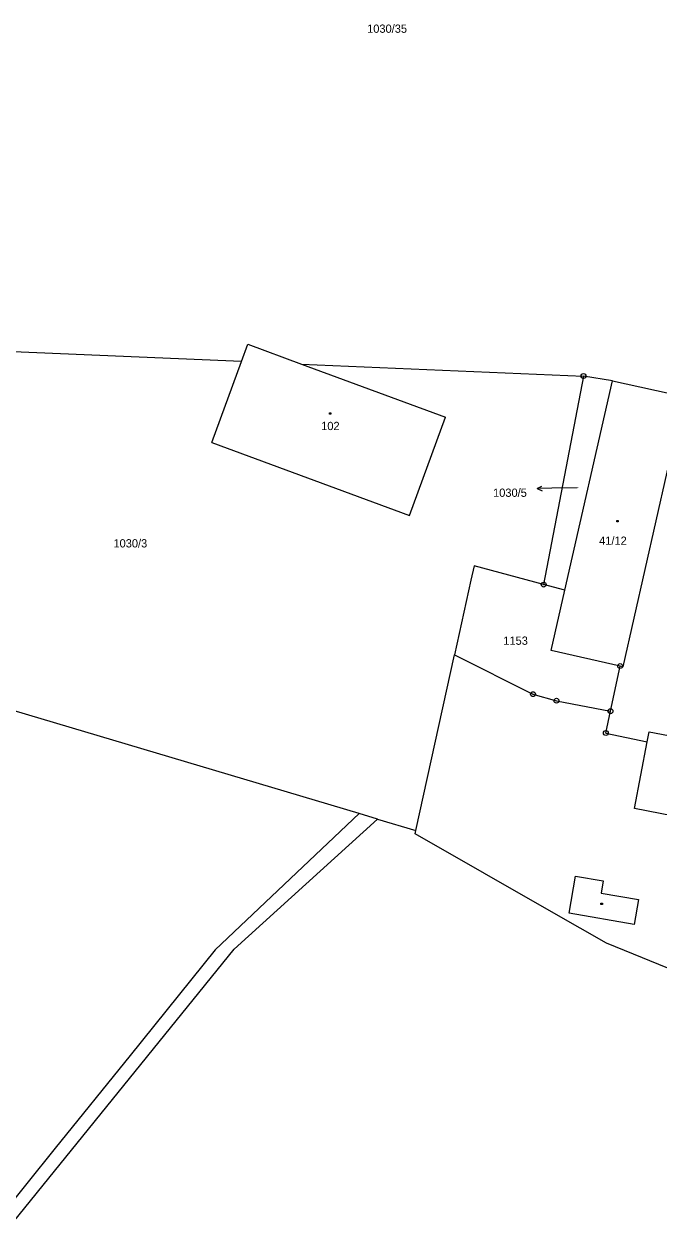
# Model space of a CAD drawing. Extents: x -794142 to -791199, y -1109267 to -1105626.
# Drawn here: x -791827.8 to -791697.1, y -1108632.2 to -1108384.2 of the extents above; entities that cross this region are included whole.
import ezdxf

# ---------------------------------------------------------------- set-up
doc = ezdxf.new("R2010")
doc.units = 0
for name, color, linetype in [('Komunikace', 7, 'Continuous'), ('Vrstva 1', 7, 'Continuous'), ('Vrstva 14', 7, 'Continuous'), ('Vrstva 15', 7, 'Continuous'), ('Vrstva 16', 7, 'Continuous'), ('Vrstva 2', 7, 'Continuous'), ('Vrstva 25', 7, 'Continuous'), ('Vrstva 28', 7, 'Continuous')]:
    doc.layers.add(name, color=color, linetype=linetype)

msp = doc.modelspace()

# ---------------------------------------------------------------- linework, layer by layer
at = {"layer": 'Komunikace'}
msp.add_line((-791713.89, -1108479.67), (-791719.17, -1108479.75), dxfattribs=at)
at = {"layer": 'Vrstva 1'}
for p, q in [((-791783.06, -1108453.63), (-791891.95, -1108449)), ((-791783.06, -1108453.63), (-791781.75, -1108450.09)), ((-791781.75, -1108450.09), (-791770.71, -1108454.16)), ((-791789.2, -1108470.31), (-791783.06, -1108453.63)), ((-791770.71, -1108454.16), (-791741.02, -1108465.1)), ((-791770.71, -1108454.16), (-791712.63, -1108456.63)), ((-791712.63, -1108456.63), (-791720.83, -1108499.57)), ((-791716.48, -1108500.74), (-791706.63, -1108457.59)), ((-791706.63, -1108457.59), (-791712.63, -1108456.63)), ((-791706.63, -1108457.59), (-791691.93, -1108460.85)), ((-791748.47, -1108485.32), (-791741.02, -1108465.1)), ((-791789.2, -1108470.31), (-791748.47, -1108485.32)), ((-791735.15, -1108495.73), (-791735.8, -1108498.66)), ((-791720.83, -1108499.57), (-791735.15, -1108495.73)), ((-791735.8, -1108498.66), (-791739.18, -1108514.04)), ((-791716.48, -1108500.74), (-791720.83, -1108499.57)), ((-791719.31, -1108513.12), (-791716.48, -1108500.74)), ((-791747.14, -1108550.19), (-791739.18, -1108514.04)), ((-791739.18, -1108514.04), (-791723.03, -1108522.13)), ((-791705.07, -1108516.34), (-791719.31, -1108513.12)), ((-791758.83, -1108546.71), (-791859.39, -1108516.79)), ((-791707.05, -1108525.63), (-791705.07, -1108516.34)), ((-791723.03, -1108522.13), (-791718.17, -1108523.48)), ((-791718.17, -1108523.48), (-791707.05, -1108525.63)), ((-791708.03, -1108530.13), (-791707.05, -1108525.63)), ((-791708.03, -1108530.13), (-791699.48, -1108531.91)), ((-791702.12, -1108545.66), (-791699.48, -1108531.91)), ((-791758.83, -1108546.71), (-791788.47, -1108574.78)), ((-791755.08, -1108547.83), (-791758.83, -1108546.71)), ((-791666.86, -1108552.44), (-791702.12, -1108545.66)), ((-791784.56, -1108574.59), (-791755.08, -1108547.83)), ((-791755.08, -1108547.83), (-791747.14, -1108550.19)), ((-791747.3, -1108550.89), (-791747.14, -1108550.19)), ((-791718.71, -1108567.18), (-791747.3, -1108550.89)), ((-791707.85, -1108573.38), (-791718.71, -1108567.18)), ((-791831.17, -1108632.21), (-791784.56, -1108574.59)), ((-791685.58, -1108582.47), (-791707.85, -1108573.38)), ((-791788.47, -1108574.78), (-791805.99, -1108596.53)), ((-791805.99, -1108596.53), (-791821.46, -1108615.59)), ((-791821.46, -1108615.59), (-791833.22, -1108630.17))]:
    msp.add_line(p, q, dxfattribs=at)
msp.add_lwpolyline([(-791699.48, -1108531.91), (-791699.09, -1108529.87), (-791662.54, -1108536.84), (-791662.89, -1108538.71)], dxfattribs=at)
at = {"layer": 'Vrstva 16'}
for p, q in [((-791722.169, -1108479.797), (-791721.177, -1108479.281)), ((-791719.17, -1108479.75), (-791722.169, -1108479.797)), ((-791722.169, -1108479.797), (-791721.161, -1108480.281))]:
    msp.add_line(p, q, dxfattribs=at)
at = {"layer": 'Vrstva 2'}
for p, q in [((-791693.19, -1108466.42), (-791704.49, -1108516.47)), ((-791704.49, -1108516.47), (-791705.07, -1108516.34)), ((-791715.55, -1108567.23), (-791714.3, -1108559.62)), ((-791714.3, -1108559.62), (-791708.58, -1108560.58)), ((-791708.58, -1108560.58), (-791709.01, -1108563.12)), ((-791709.01, -1108563.12), (-791701.3, -1108564.43)), ((-791701.3, -1108564.43), (-791702.17, -1108569.51)), ((-791702.17, -1108569.51), (-791715.55, -1108567.23))]:
    msp.add_line(p, q, dxfattribs=at)
at = {"layer": 'Vrstva 25'}
for p, q in [((-791764.93, -1108464.21), (-791764.63, -1108464.21)), ((-791764.93, -1108464.51), (-791764.93, -1108464.21)), ((-791764.63, -1108464.51), (-791764.93, -1108464.51)), ((-791764.63, -1108464.21), (-791764.63, -1108464.51)), ((-791705.76, -1108486.36), (-791705.46, -1108486.36)), ((-791705.76, -1108486.66), (-791705.76, -1108486.36)), ((-791705.46, -1108486.66), (-791705.76, -1108486.66)), ((-791705.46, -1108486.36), (-791705.46, -1108486.66)), ((-791709.02, -1108565.16), (-791708.72, -1108565.16)), ((-791709.02, -1108565.46), (-791709.02, -1108565.16)), ((-791708.72, -1108565.46), (-791709.02, -1108565.46)), ((-791708.72, -1108565.16), (-791708.72, -1108565.46))]:
    msp.add_line(p, q, dxfattribs=at)
at = {"layer": 'Vrstva 28'}
for centre, radius in [((-791712.63, -1108456.63), 0.5), ((-791712.63, -1108456.63), 0.01), ((-791720.83, -1108499.57), 0.5), ((-791720.83, -1108499.57), 0.01), ((-791705.07, -1108516.34), 0.5), ((-791705.07, -1108516.34), 0.01), ((-791723.03, -1108522.13), 0.5), ((-791723.03, -1108522.13), 0.01), ((-791718.17, -1108523.48), 0.5), ((-791718.17, -1108523.48), 0.01), ((-791707.05, -1108525.63), 0.5), ((-791707.05, -1108525.63), 0.01), ((-791708.03, -1108530.13), 0.5), ((-791708.03, -1108530.13), 0.01)]:
    msp.add_circle(centre, radius, dxfattribs=at)

# ---------------------------------------------------------------- texts
at = {"layer": 'Vrstva 14'}
for s, height, p in [('1030/35', 1.7, (-791757.188, -1108385.97)), ('1030/5', 0.1, (-791714.127, -1108479.67)), ('1030/3', 1.7, (-791809.442, -1108491.92)), ('1153', 1.7, (-791729.139, -1108511.96))]:
    msp.add_text(s, height=height, dxfattribs=at).set_placement(p)
at = {"layer": 'Vrstva 15'}
for s, p in [('102', (-791766.649, -1108467.76)), ('41/12', (-791709.402, -1108491.38))]:
    msp.add_text(s, height=1.7, dxfattribs=at).set_placement(p)
at = {"layer": 'Vrstva 16'}
msp.add_text('1030/5', height=1.7, dxfattribs=at).set_placement((-791731.246, -1108481.5))

doc.saveas('drawing.dxf')
